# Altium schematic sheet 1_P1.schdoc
size 309 x 223 mm; Symbol: Sheet-Symbol_A4; Device: Sheet-Symbol_A4; Company: 嘉立创EDA; Version: V1.0; Page Size: A4; @Project Name: paw3205db测试板; @Page Count: 1; @Update Date: 2024-11-19; @Create Date: 2024-11-18; @Schematic Name: Schematic1; @Page No: 1; @Page Name: P1; @Board Name: Board1; @Create Time: 23:53:41; @Update Time: 00:17:56
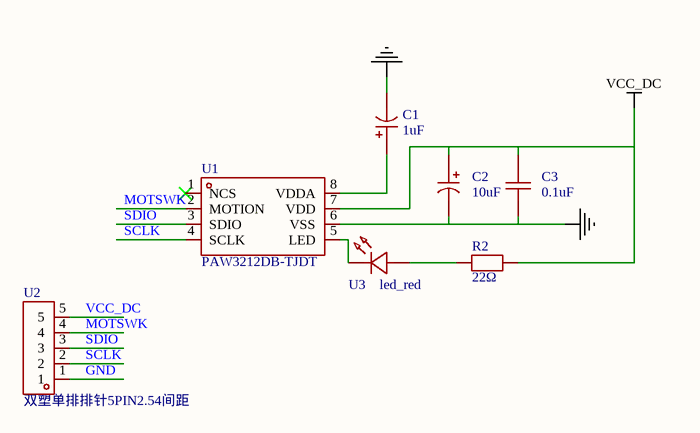
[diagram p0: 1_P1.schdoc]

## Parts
C1  1uF  [CAP-TH_BD6.0-P2.50-D0.5-FD]  (value not drawn)
C2  10uF  [CAP-TH_BD6.0-P2.50-D0.5-FD]  (value not drawn)
C3  0.1uF  [CAP-TH_L4.2-W3.5-P2.54-D0.5]  (value not drawn)
R2  22Ω  [RES-TH_BD2.7-L6.2-P10.20-D0.4]  (value not drawn)
U1  PAW3212DB-TJDT  [SENSOR-TH_PAW3212DB-TJDT]  (value not drawn)
U2  双塑单排排针5PIN2.54间距  [HDR-TH_5P-P2.54-V-M-A]  (value not drawn)
U3  led_red  [LED-TH_BD5.0-P2.54-FD]  (value not drawn)

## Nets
GND: C1.2 C2.2 C3.1 U1.6(VSS) U2.1
VCC_DC: C2.1 C3.2 R2.2 U1.7(VDD) U2.5
MOTSWK: U1.2(MOTION) U2.4
SCLK: U1.4(SCLK) U2.2
SDIO: U1.3(SDIO) U2.3
NetC1_1: C1.1 U1.8(VDDA)
NetR2_1: R2.1 U3.1(A)
NetU1_5: U1.5(LED) U3.2(K)

Not connected (* = marked no-connect by the designer): U1 1(NCS)*

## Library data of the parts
C1 C2 = CD110477M1A0607VFL: 容值:470uF;额定电压:10V;; Manufacturer: HRK(鸿瑞凯电子); Add into BOM: yes; Rated Voltage: 10V; φD: 6mm; L: 7mm
C3 = 178MU0006: 容值:100nF;精度:±10%;额定电压:50V;温度系数:X7R;; Manufacturer: KNSCHA(科尼盛); Add into BOM: yes; Tolerance: ±10%; Voltage Rated: 50V; Temperature Coefficient: X7R
R2 = MF1/4W-1K±1%-ST52: 电阻类型:金属膜电阻;阻值:1kΩ;精度:±1%;功率:250mW;温度系数:±100ppm/℃;; Manufacturer: VO(翔胜); Add into BOM: yes; Tolerance: ±1%; Overload Voltage (Max): 250V; Power(Watts): 250mW
U1 = PAW3212DB-TJDT: Add into BOM: yes
U2 = 双塑单排排针5PIN2.54间距: Add into BOM: yes
U3 = MHL5013UGTC: 发光颜色:绿色;正向电压(VF):2.8V~3.4V;正向电流:20mA;主波长:515nm~525nm;透镜颜色:-;发光强度:26000mcd;发光角度:30°;工作温度:-40℃~+85℃;; Manufacturer: MEIHUA(美华); Add into BOM: yes; Emitted Color: 绿色; Forward Current: 20mA; Viewing Angle: 30°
